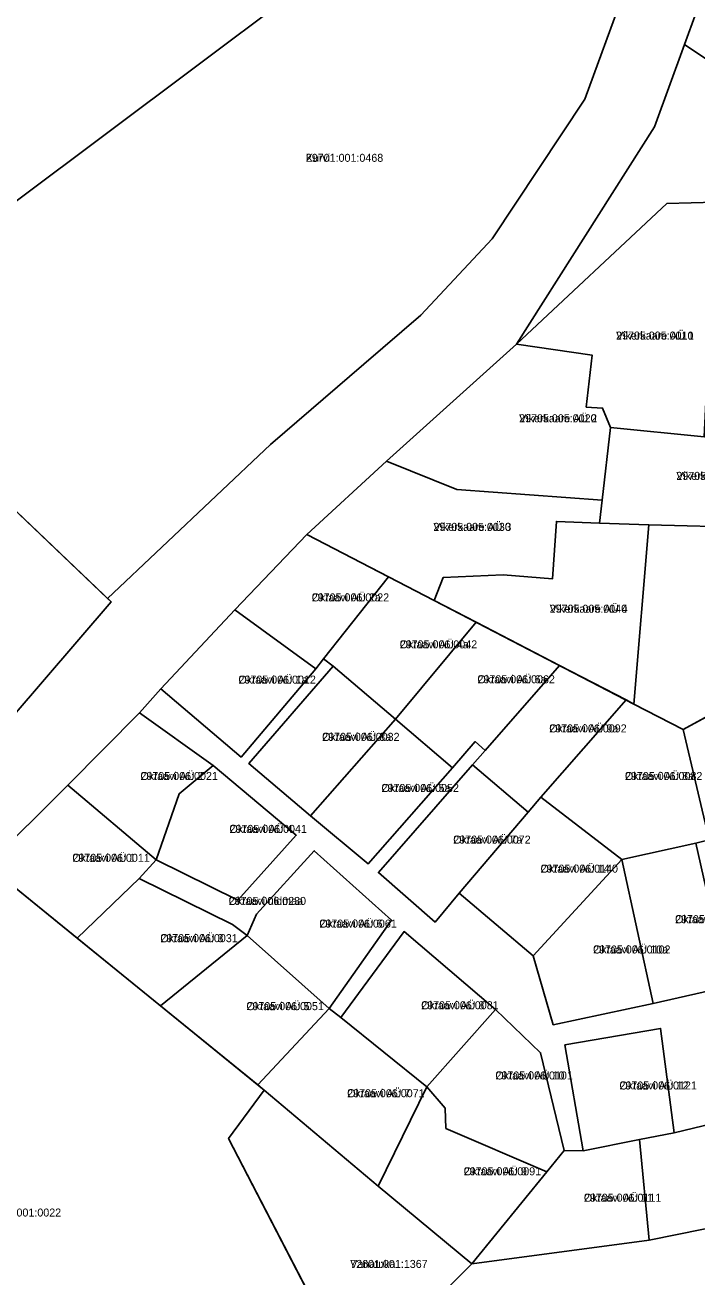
# Model space of a CAD drawing. Extents: x 504287 to 537970, y 6539941 to 6586214.
# Drawn here: x 519008.5 to 519134.4, y 6563201.2 to 6563435.8 of the extents above; entities that cross this region are included whole.
import ezdxf

# ---------------------------------------------------------------- set-up
doc = ezdxf.new("R2010")
doc.units = 0
for name, color, linetype in [('L_AADRESS', 7, 'Continuous'), ('PIIR', 7, 'Continuous'), ('TUNNUS', 7, 'Continuous')]:
    doc.layers.add(name, color=color, linetype=linetype)

msp = doc.modelspace()

# ---------------------------------------------------------------- linework, layer by layer
at = {"layer": 'PIIR'}
for points in [[(519106.92, 6563575.23), (519114.51, 6563550.25), (519122.8, 6563515.72), (519125.84, 6563492.01), (518972.74, 6563377.25), (518891.28, 6563275.18), (518880.12, 6563290.99), (518869.03, 6563306.7), (518865.74, 6563311.37), (518847.6, 6563335.86)], [(519140.05, 6563476.97), (519153.68, 6563480.42), (519218.45, 6563486.02), (519326.38, 6563519.01), (519226.15, 6563445.74), (519200.78, 6563430.75), (519200.34, 6563424.73), (519200.43, 6563394.25), (519200.26, 6563378.22), (519200.3, 6563363.09), (519200.34, 6563349.64), (519200.31, 6563340.52), (519160.99, 6563412.72), (519132.07, 6563432.14), (519134.26, 6563438.15), (519138.11, 6563452.64)], [(518972.74, 6563377.25), (519125.84, 6563492.01), (519126.03, 6563477.91), (519120.61, 6563441.57), (519113.44, 6563421.94), (519096.05, 6563395.74), (519082.7, 6563381.42), (519072.01, 6563372.24), (519054.51, 6563357.21), (519024, 6563328.33)], [(519116.74, 6563364.03), (519113.68, 6563364.22), (519114.8, 6563373.92), (519100.63, 6563375.97), (519128.79, 6563402.34), (519137.88, 6563402.61), (519135.78, 6563358.63), (519118.22, 6563360.41)], [(519116.13, 6563342.47), (519116.63, 6563346.75), (519118.22, 6563360.41), (519135.78, 6563358.63), (519137.88, 6563402.61), (519144.03, 6563402.9), (519142.15, 6563362.74), (519141.4, 6563348.02), (519144.96, 6563347.74), (519144.6, 6563341.63), (519125.43, 6563342.12)], [(519024.68, 6563327.68), (518931.09, 6563218.79), (518891.28, 6563275.18), (518972.74, 6563377.25)], [(519076.24, 6563354.07), (519100.63, 6563375.97), (519114.8, 6563373.92), (519113.68, 6563364.22), (519116.74, 6563364.03), (519118.22, 6563360.41), (519116.63, 6563346.75), (519089.43, 6563348.75)], [(519085.21, 6563327.95), (519061.36, 6563340.32), (519076.24, 6563354.07), (519089.43, 6563348.75), (519116.63, 6563346.75), (519116.13, 6563342.47), (519108.1, 6563342.79), (519107.33, 6563332.01), (519098.13, 6563332.77), (519086.89, 6563332.28)], [(519086.89, 6563332.28), (519098.13, 6563332.77), (519107.33, 6563332.01), (519108.1, 6563342.79), (519116.13, 6563342.47), (519125.43, 6563342.12), (519122.62, 6563308.55), (519085.21, 6563327.95)], [(519122.62, 6563308.55), (519125.43, 6563342.12), (519144.6, 6563341.63), (519143.81, 6563333.54), (519146.43, 6563333.37), (519146.02, 6563311.51), (519131.85, 6563303.77)], [(519061.36, 6563340.32), (519076.65, 6563332.39), (519064.43, 6563317), (519063.04, 6563315.15), (519047.86, 6563326.2)], [(519066.28, 6563315.63), (519064.43, 6563317), (519076.65, 6563332.39), (519085.21, 6563327.95), (519093.05, 6563323.88), (519077.94, 6563305.71)], [(519047.86, 6563326.2), (519063.04, 6563315.15), (519049.02, 6563298.62), (519034, 6563311.4)], [(519077.94, 6563305.71), (519093.05, 6563323.88), (519108.67, 6563315.78), (519094.76, 6563299.86), (519092.89, 6563301.52), (519088.61, 6563296.63)], [(519050.47, 6563297.4), (519066.28, 6563315.63), (519077.94, 6563305.71), (519062.02, 6563287.59)], [(519102.78, 6563288.28), (519092.37, 6563297.14), (519094.76, 6563299.86), (519108.67, 6563315.78), (519121.14, 6563309.32), (519105.18, 6563291.09)], [(519131.85, 6563303.77), (519145.06, 6563310.99), (519151.13, 6563285.44), (519136.69, 6563283.13)], [(519121.14, 6563309.32), (519122.62, 6563308.55), (519131.85, 6563303.77), (519136.69, 6563283.13), (519134.19, 6563282.46), (519120.36, 6563279.43), (519105.18, 6563291.09)], [(519029.99, 6563306.91), (519043.77, 6563297.03), (519037.44, 6563291.74), (519033.08, 6563279.38), (519016.55, 6563293.33)], [(519062.02, 6563287.59), (519077.94, 6563305.71), (519088.61, 6563296.63), (519072.85, 6563278.61)], [(519037.44, 6563291.74), (519043.77, 6563297.03), (519059.36, 6563283.97), (519048.38, 6563271.79), (519033.08, 6563279.38)], [(519074.74, 6563276.96), (519092.37, 6563297.14), (519102.78, 6563288.28), (519089.88, 6563273.14), (519085.36, 6563267.7)], [(519016.55, 6563293.33), (519033.08, 6563279.38), (519029.92, 6563275.87), (519018.27, 6563264.66), (519001.41, 6563278.34)], [(519089.88, 6563273.14), (519102.78, 6563288.28), (519105.18, 6563291.09), (519120.36, 6563279.43), (519103.73, 6563261.39)], [(519120.36, 6563279.43), (519134.19, 6563282.46), (519140.28, 6563255.61), (519126.2, 6563252.44)], [(519051.87, 6563269.2), (519062.71, 6563281.05), (519077.2, 6563268.03), (519065.49, 6563251.53), (519050.16, 6563265.2)], [(519053.34, 6563236.21), (519046.68, 6563227.13), (519070.28, 6563181.56), (519010.92, 6563141.43), (518931.33, 6563188.8), (519001.41, 6563278.34)], [(519103.73, 6563261.39), (519120.36, 6563279.43), (519126.2, 6563252.44), (519107.51, 6563248.45)], [(519018.27, 6563264.66), (519029.92, 6563275.87), (519047.39, 6563267.21), (519050.16, 6563265.2), (519033.9, 6563251.98)], [(519079.56, 6563265.9), (519096.66, 6563251.34), (519083.8, 6563236.82), (519067.73, 6563249.79)], [(519050.16, 6563265.2), (519065.49, 6563251.53), (519052.15, 6563237.18), (519033.9, 6563251.98)], [(519065.49, 6563251.53), (519067.73, 6563249.79), (519083.8, 6563236.82), (519074.71, 6563218.2), (519053.34, 6563236.21), (519052.15, 6563237.18)], [(519087.25, 6563232.83), (519083.8, 6563236.82), (519096.66, 6563251.34), (519105.12, 6563243.2), (519109.53, 6563224.88), (519106.29, 6563220.92), (519087.39, 6563229.04)], [(519109.67, 6563244.69), (519127.6, 6563247.78), (519130.13, 6563228.2), (519123.65, 6563226.94), (519113.11, 6563224.83)], [(519236.2, 6563238.48), (519243.47, 6563223.81), (519238.26, 6563225.44), (519213.24, 6563217.67), (519209.13, 6563216.28), (519182.57, 6563208.19), (519141.33, 6563199.52), (519136.15, 6563198.16), (519102.94, 6563190.91), (519097.15, 6563189.57), (519075.1, 6563172.56), (519071.2, 6563169.74), (519047.83, 6563153.98), (519019.15, 6563136.44), (519010.92, 6563141.43), (519070.28, 6563181.56), (519092.24, 6563203.65), (519125.45, 6563208.08), (519151.08, 6563213.3), (519170.59, 6563217.51), (519190.06, 6563221.91), (519216.47, 6563228.93)], [(519070.28, 6563181.56), (519070.12, 6563181.87), (519046.68, 6563227.13), (519053.32, 6563236.18), (519074.71, 6563218.2), (519092.24, 6563203.65)], [(519083.8, 6563236.82), (519087.25, 6563232.83), (519087.39, 6563229.04), (519106.29, 6563220.92), (519092.24, 6563203.65), (519074.71, 6563218.2)], [(519123.65, 6563226.94), (519130.13, 6563228.2), (519140.76, 6563230.74), (519146.21, 6563228.27), (519145.7, 6563222.39), (519151.08, 6563213.3), (519125.45, 6563208.08)], [(519106.29, 6563220.92), (519109.53, 6563224.88), (519113.11, 6563224.83), (519123.65, 6563226.94), (519125.45, 6563208.08), (519092.24, 6563203.65)]]:
    msp.add_lwpolyline(points, close=True, dxfattribs=at)
for points in [[(518931.09, 6563218.79), (519024.68, 6563327.68), (519024, 6563328.33), (519054.51, 6563357.21), (519072.01, 6563372.24), (519082.7, 6563381.42), (519096.05, 6563395.74), (519113.44, 6563421.94), (519120.61, 6563441.57)], [(519134.26, 6563438.15), (519132.07, 6563432.14), (519126.46, 6563416.73), (519100.63, 6563375.97), (519076.24, 6563354.07), (519061.36, 6563340.32), (519047.86, 6563326.2), (519034, 6563311.4), (519029.99, 6563306.91), (519016.55, 6563293.33), (519001.41, 6563278.34)], [(519137.88, 6563402.61), (519128.79, 6563402.34), (519100.63, 6563375.97), (519126.46, 6563416.73), (519132.07, 6563432.14), (519160.99, 6563412.72)], [(519140.76, 6563230.74), (519130.13, 6563228.2), (519127.6, 6563247.78), (519109.67, 6563244.69), (519113.11, 6563224.83), (519109.53, 6563224.88), (519105.12, 6563243.2), (519096.66, 6563251.34), (519079.56, 6563265.9), (519067.73, 6563249.79), (519065.49, 6563251.53), (519077.2, 6563268.03), (519062.71, 6563281.05), (519051.87, 6563269.2), (519050.16, 6563265.2), (519047.39, 6563267.21), (519029.92, 6563275.87), (519033.08, 6563279.38), (519048.38, 6563271.79), (519059.36, 6563283.97), (519043.77, 6563297.03), (519029.99, 6563306.91), (519034, 6563311.4), (519049.02, 6563298.62), (519063.04, 6563315.15), (519064.43, 6563317), (519066.28, 6563315.63), (519050.47, 6563297.4), (519062.02, 6563287.59), (519072.85, 6563278.61), (519088.61, 6563296.63), (519092.89, 6563301.52), (519094.76, 6563299.86), (519092.37, 6563297.14), (519074.74, 6563276.96), (519085.36, 6563267.7), (519089.88, 6563273.14), (519103.73, 6563261.39), (519107.51, 6563248.45), (519126.2, 6563252.44), (519140.28, 6563255.61), (519134.19, 6563282.46), (519136.69, 6563283.13)]]:
    msp.add_lwpolyline(points, dxfattribs=at)

# ---------------------------------------------------------------- texts
at = {"layer": 'L_AADRESS'}
for s, p in [('Kurvi', (519061.14, 6563410.17)), ('Vikerkaare AÜ 1', (519119.26, 6563376.86)), ('Vikerkaare AÜ 2', (519101.1, 6563361.36)), ('Vikerkaare üldmaa', (519130.55, 6563350.57)), ('Vikerkaare AÜ 3', (519085.04, 6563341.01)), ('Oktaavi AÜ 2a', (519062.25, 6563327.79)), ('Vikerkaare AÜ 4', (519106.83, 6563325.67)), ('Oktaavi AÜ 4a', (519078.74, 6563318.99)), ('Oktaavi AÜ 1a', (519048.52, 6563312.38)), ('Oktaavi AÜ 6a', (519093.3, 6563312.45)), ('Oktaavi AÜ 3a', (519064.2, 6563301.66)), ('Oktaavi AÜ 9a', (519106.75, 6563303.24)), ('Oktaavi AÜ 2', (519030.16, 6563294.32)), ('Oktaavi AÜ 8a', (519120.93, 6563294.32)), ('Oktaavi AÜ 5a', (519075.32, 6563292.08)), ('Oktaavi AÜ 4', (519046.84, 6563284.41)), ('Oktaavi AÜ 7a', (519088.76, 6563282.4)), ('Oktaavi AÜ 1', (519017.4, 6563278.99)), ('Oktaavi AÜ 14', (519105.12, 6563276.96)), ('Oktaavi üldmaa', (519046.68, 6563270.91)), ('Oktaavi AÜ 6', (519063.68, 6563266.66)), ('Oktaavi AÜ 11a', (519130.32, 6563267.49)), ('Oktaavi AÜ 3', (519033.88, 6563263.93)), ('Oktaavi AÜ 10a', (519114.96, 6563261.81)), ('Oktaavi AÜ 5', (519050.02, 6563251.19)), ('Oktaavi AÜ 8', (519082.76, 6563251.36)), ('Oktaavi AÜ 10', (519096.66, 6563238.2)), ('Oktaavi AÜ 12', (519119.9, 6563236.32)), ('Oktaavi AÜ 7', (519068.89, 6563234.87)), ('Oktaavi AÜ 9', (519090.72, 6563220.24)), ('Oktaavi AÜ 11', (519113.24, 6563215.29)), ('Vanatuka', (519069.46, 6563202.88))]:
    msp.add_text(s, height=1.5, dxfattribs=at).set_placement(p)
at = {"layer": 'TUNNUS'}
for s, p in [('29701:001:0468', (519061.14, 6563410.17)), ('29705:005:0010', (519119.26, 6563376.86)), ('29705:005:0020', (519101.1, 6563361.36)), ('29705:005:0090', (519130.55, 6563350.57)), ('29705:005:0030', (519085.04, 6563341.01)), ('29705:006:0022', (519062.25, 6563327.79)), ('29705:005:0040', (519106.83, 6563325.67)), ('29705:006:0042', (519078.74, 6563318.99)), ('29705:006:0012', (519048.52, 6563312.38)), ('29705:006:0062', (519093.3, 6563312.45)), ('29705:006:0032', (519064.2, 6563301.66)), ('29705:006:0092', (519106.75, 6563303.24)), ('29705:006:0021', (519030.16, 6563294.32)), ('29705:006:0082', (519120.93, 6563294.32)), ('29705:006:0052', (519075.32, 6563292.08)), ('29705:006:0041', (519046.84, 6563284.41)), ('29705:006:0072', (519088.76, 6563282.4)), ('29705:006:0011', (519017.4, 6563278.99)), ('29705:006:0140', (519105.12, 6563276.96)), ('29705:006:0230', (519046.68, 6563270.91)), ('29705:006:0061', (519063.68, 6563266.66)), ('29705:006:0112', (519130.32, 6563267.49)), ('29705:006:0031', (519033.88, 6563263.93)), ('29705:006:0102', (519114.96, 6563261.81)), ('29705:006:0051', (519050.02, 6563251.19)), ('29705:006:0081', (519082.76, 6563251.36)), ('29705:006:0101', (519096.66, 6563238.2)), ('29705:006:0121', (519119.9, 6563236.32)), ('29705:006:0071', (519068.89, 6563234.87)), ('29705:006:0091', (519090.72, 6563220.24)), ('29705:006:0111', (519113.24, 6563215.29)), ('29705:001:0022', (519000.8, 6563212.51)), ('72601:001:1367', (519069.46, 6563202.88))]:
    msp.add_text(s, height=1.5, dxfattribs=at).set_placement(p)

doc.saveas('drawing.dxf')
